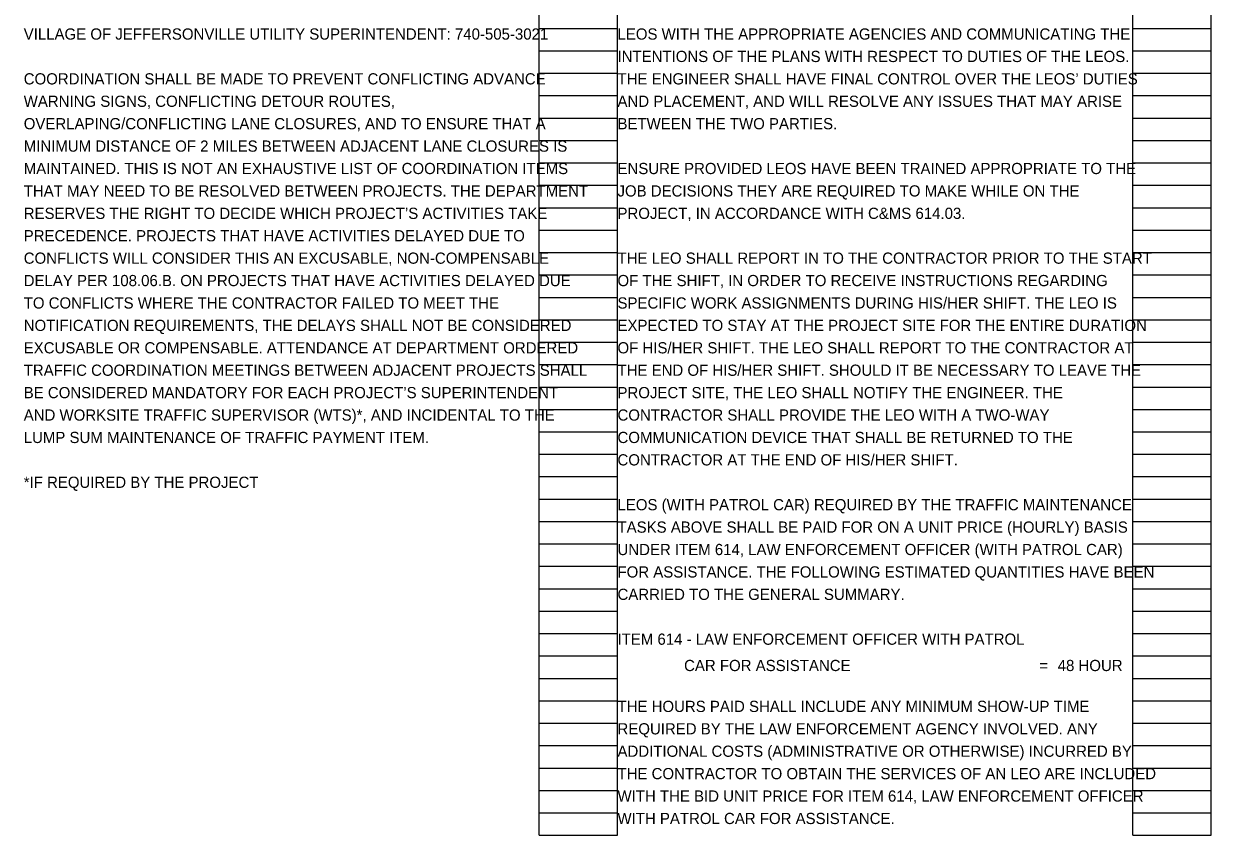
# Model space of a CAD drawing. Extents: x 37613.4 to 37668.4, y 18853.7 to 18946.8.
# Drawn here: x 37638.8 to 37653.64, y 18897.52 to 18907.66 of the extents above; entities that cross this region are included whole.
import ezdxf

# ---------------------------------------------------------------- set-up
doc = ezdxf.new("R2010")
doc.units = 0
doc.layers.add('SH_Data', color=7, linetype='Continuous')
doc.layers.add('SH_Text', color=7, linetype='Continuous')

msp = doc.modelspace()

# ---------------------------------------------------------------- linework, layer by layer
at = {"layer": 'SH_Data'}
for p, q in [((37645.241, 18897.522), (37645.241, 18917.682)), ((37646.221, 18897.522), (37646.221, 18917.682)), ((37652.661, 18897.522), (37652.661, 18917.682)), ((37653.641, 18897.522), (37653.641, 18917.682)), ((37645.241, 18907.602), (37646.221, 18907.602)), ((37652.661, 18907.602), (37653.641, 18907.602)), ((37645.241, 18907.322), (37646.221, 18907.322)), ((37652.661, 18907.322), (37653.641, 18907.322)), ((37645.241, 18907.042), (37646.221, 18907.042)), ((37652.661, 18907.042), (37653.641, 18907.042)), ((37645.241, 18906.762), (37646.221, 18906.762)), ((37652.661, 18906.762), (37653.641, 18906.762)), ((37645.241, 18906.482), (37646.221, 18906.482)), ((37652.661, 18906.482), (37653.641, 18906.482)), ((37645.241, 18906.202), (37646.221, 18906.202)), ((37652.661, 18906.202), (37653.641, 18906.202)), ((37645.241, 18905.922), (37646.221, 18905.922)), ((37652.661, 18905.922), (37653.641, 18905.922)), ((37645.241, 18905.642), (37646.221, 18905.642)), ((37652.661, 18905.642), (37653.641, 18905.642)), ((37645.241, 18905.362), (37646.221, 18905.362)), ((37652.661, 18905.362), (37653.641, 18905.362)), ((37645.241, 18905.082), (37646.221, 18905.082)), ((37652.661, 18905.082), (37653.641, 18905.082)), ((37645.241, 18904.802), (37646.221, 18904.802)), ((37652.661, 18904.802), (37653.641, 18904.802)), ((37645.241, 18904.522), (37646.221, 18904.522)), ((37652.661, 18904.522), (37653.641, 18904.522)), ((37645.241, 18904.242), (37646.221, 18904.242)), ((37652.661, 18904.242), (37653.641, 18904.242)), ((37645.241, 18903.962), (37646.221, 18903.962)), ((37652.661, 18903.962), (37653.641, 18903.962)), ((37645.241, 18903.682), (37646.221, 18903.682)), ((37652.661, 18903.682), (37653.641, 18903.682)), ((37645.241, 18903.402), (37646.221, 18903.402)), ((37652.661, 18903.402), (37653.641, 18903.402)), ((37645.241, 18903.122), (37646.221, 18903.122)), ((37652.661, 18903.122), (37653.641, 18903.122)), ((37645.241, 18902.842), (37646.221, 18902.842)), ((37652.661, 18902.842), (37653.641, 18902.842)), ((37645.241, 18902.562), (37646.221, 18902.562)), ((37652.661, 18902.562), (37653.641, 18902.562)), ((37645.241, 18902.282), (37646.221, 18902.282)), ((37652.661, 18902.282), (37653.641, 18902.282)), ((37645.241, 18902.002), (37646.221, 18902.002)), ((37652.661, 18902.002), (37653.641, 18902.002)), ((37645.241, 18901.722), (37646.221, 18901.722)), ((37652.661, 18901.722), (37653.641, 18901.722)), ((37645.241, 18901.442), (37646.221, 18901.442)), ((37652.661, 18901.442), (37653.641, 18901.442)), ((37645.241, 18901.162), (37646.221, 18901.162)), ((37652.661, 18901.162), (37653.641, 18901.162)), ((37645.241, 18900.882), (37646.221, 18900.882)), ((37652.661, 18900.882), (37653.641, 18900.882)), ((37645.241, 18900.602), (37646.221, 18900.602)), ((37652.661, 18900.602), (37653.641, 18900.602)), ((37645.241, 18900.322), (37646.221, 18900.322)), ((37652.661, 18900.322), (37653.641, 18900.322)), ((37645.241, 18900.042), (37646.221, 18900.042)), ((37652.661, 18900.042), (37653.641, 18900.042)), ((37645.241, 18899.762), (37646.221, 18899.762)), ((37652.661, 18899.762), (37653.641, 18899.762)), ((37645.241, 18899.482), (37646.221, 18899.482)), ((37652.661, 18899.482), (37653.641, 18899.482)), ((37645.241, 18899.202), (37646.221, 18899.202)), ((37652.661, 18899.202), (37653.641, 18899.202)), ((37645.241, 18898.922), (37646.221, 18898.922)), ((37652.661, 18898.922), (37653.641, 18898.922)), ((37645.241, 18898.642), (37646.221, 18898.642)), ((37652.661, 18898.642), (37653.641, 18898.642)), ((37645.241, 18898.362), (37646.221, 18898.362)), ((37652.661, 18898.362), (37653.641, 18898.362)), ((37645.241, 18898.082), (37646.221, 18898.082)), ((37652.661, 18898.082), (37653.641, 18898.082)), ((37645.241, 18897.802), (37646.221, 18897.802)), ((37652.661, 18897.802), (37653.641, 18897.802)), ((37645.241, 18897.522), (37646.221, 18897.522)), ((37652.661, 18897.522), (37653.641, 18897.522))]:
    msp.add_line(p, q, dxfattribs=at)

# ---------------------------------------------------------------- texts
for s, p in [('LEOS (WITH PATROL CAR) REQUIRED BY THE TRAFFIC MAINTENANCE ', (37646.221, 18901.582)), ('TASKS ABOVE SHALL BE PAID FOR ON A UNIT PRICE (HOURLY) BASIS ', (37646.221, 18901.302)), ('UNDER ITEM 614, LAW ENFORCEMENT OFFICER (WITH PATROL CAR) ', (37646.221, 18901.022)), ('FOR ASSISTANCE. THE FOLLOWING ESTIMATED QUANTITIES HAVE BEEN ', (37646.221, 18900.742)), ('CARRIED TO THE GENERAL SUMMARY.', (37646.221, 18900.462)), ('THE HOURS PAID SHALL INCLUDE ANY MINIMUM SHOW-UP TIME ', (37646.221, 18899.062)), ('REQUIRED BY THE LAW ENFORCEMENT AGENCY INVOLVED. ANY ', (37646.221, 18898.782)), ('ADDITIONAL COSTS (ADMINISTRATIVE OR OTHERWISE) INCURRED BY ', (37646.221, 18898.502)), ('THE CONTRACTOR TO OBTAIN THE SERVICES OF AN LEO ARE INCLUDED ', (37646.221, 18898.222)), ('WITH THE BID UNIT PRICE FOR ITEM 614, LAW ENFORCEMENT OFFICER ', (37646.221, 18897.942)), ('WITH PATROL CAR FOR ASSISTANCE.', (37646.221, 18897.662))]:
    msp.add_text(s, height=0.14, dxfattribs=at).set_placement(p)
at = {"layer": 'SH_Text'}
for s, p in [('VILLAGE OF JEFFERSONVILLE UTILITY SUPERINTENDENT: 740-505-3021', (37638.801, 18907.462)), ('LEOS WITH THE APPROPRIATE AGENCIES AND COMMUNICATING THE ', (37646.221, 18907.462)), ('INTENTIONS OF THE PLANS WITH RESPECT TO DUTIES OF THE LEOS. ', (37646.221, 18907.182)), ('COORDINATION SHALL BE MADE TO PREVENT CONFLICTING ADVANCE ', (37638.801, 18906.902)), ('THE ENGINEER SHALL HAVE FINAL CONTROL OVER THE LEOS’ DUTIES ', (37646.221, 18906.902)), ('WARNING SIGNS, CONFLICTING DETOUR ROUTES, ', (37638.801, 18906.622)), ('AND PLACEMENT, AND WILL RESOLVE ANY ISSUES THAT MAY ARISE ', (37646.221, 18906.622)), ('OVERLAPING/CONFLICTING LANE CLOSURES, AND TO ENSURE THAT A ', (37638.801, 18906.342)), ('BETWEEN THE TWO PARTIES. ', (37646.221, 18906.342)), ('MINIMUM DISTANCE OF 2 MILES BETWEEN ADJACENT LANE CLOSURES IS ', (37638.801, 18906.062)), ('MAINTAINED. THIS IS NOT AN EXHAUSTIVE LIST OF COORDINATION ITEMS ', (37638.801, 18905.782)), ('ENSURE PROVIDED LEOS HAVE BEEN TRAINED APPROPRIATE TO THE ', (37646.221, 18905.782)), ('THAT MAY NEED TO BE RESOLVED BETWEEN PROJECTS. THE DEPARTMENT ', (37638.801, 18905.502)), ('JOB DECISIONS THEY ARE REQUIRED TO MAKE WHILE ON THE ', (37646.221, 18905.502)), ('RESERVES THE RIGHT TO DECIDE WHICH PROJECT’S ACTIVITIES TAKE ', (37638.801, 18905.222)), ('PROJECT, IN ACCORDANCE WITH C&MS 614.03. ', (37646.221, 18905.222)), ('PRECEDENCE. PROJECTS THAT HAVE ACTIVITIES DELAYED DUE TO ', (37638.801, 18904.942)), ('CONFLICTS WILL CONSIDER THIS AN EXCUSABLE, NON-COMPENSABLE ', (37638.801, 18904.662)), ('THE LEO SHALL REPORT IN TO THE CONTRACTOR PRIOR TO THE START ', (37646.221, 18904.662)), ('DELAY PER 108.06.B. ON PROJECTS THAT HAVE ACTIVITIES DELAYED DUE ', (37638.801, 18904.382)), ('OF THE SHIFT, IN ORDER TO RECEIVE INSTRUCTIONS REGARDING ', (37646.221, 18904.382)), ('TO CONFLICTS WHERE THE CONTRACTOR FAILED TO MEET THE ', (37638.801, 18904.102)), ('SPECIFIC WORK ASSIGNMENTS DURING HIS/HER SHIFT. THE LEO IS ', (37646.221, 18904.102)), ('NOTIFICATION REQUIREMENTS, THE DELAYS SHALL NOT BE CONSIDERED ', (37638.801, 18903.822)), ('EXPECTED TO STAY AT THE PROJECT SITE FOR THE ENTIRE DURATION ', (37646.221, 18903.822)), ('EXCUSABLE OR COMPENSABLE. ATTENDANCE AT DEPARTMENT ORDERED ', (37638.801, 18903.542)), ('OF HIS/HER SHIFT. THE LEO SHALL REPORT TO THE CONTRACTOR AT ', (37646.221, 18903.542)), ('TRAFFIC COORDINATION MEETINGS BETWEEN ADJACENT PROJECTS SHALL ', (37638.801, 18903.262)), ('THE END OF HIS/HER SHIFT. SHOULD IT BE NECESSARY TO LEAVE THE ', (37646.221, 18903.262)), ('BE CONSIDERED MANDATORY FOR EACH PROJECT’S SUPERINTENDENT ', (37638.801, 18902.982)), ('PROJECT SITE, THE LEO SHALL NOTIFY THE ENGINEER. THE ', (37646.221, 18902.982)), ('AND WORKSITE TRAFFIC SUPERVISOR (WTS)*, AND INCIDENTAL TO THE ', (37638.801, 18902.702)), ('CONTRACTOR SHALL PROVIDE THE LEO WITH A TWO-WAY ', (37646.221, 18902.702)), ('LUMP SUM MAINTENANCE OF TRAFFIC PAYMENT ITEM.', (37638.801, 18902.422)), ('COMMUNICATION DEVICE THAT SHALL BE RETURNED TO THE ', (37646.221, 18902.422)), ('CONTRACTOR AT THE END OF HIS/HER SHIFT.', (37646.221, 18902.142)), ('*IF REQUIRED BY THE PROJECT', (37638.801, 18901.862)), ('ITEM 614 - LAW ENFORCEMENT OFFICER WITH PATROL', (37646.221, 18899.902)), ('                CAR FOR ASSISTANCE', (37646.221, 18899.573)), ('=', (37651.493, 18899.573)), ('48 HOUR', (37651.722, 18899.573))]:
    msp.add_text(s, height=0.14, dxfattribs=at).set_placement(p)

doc.saveas('drawing.dxf')
